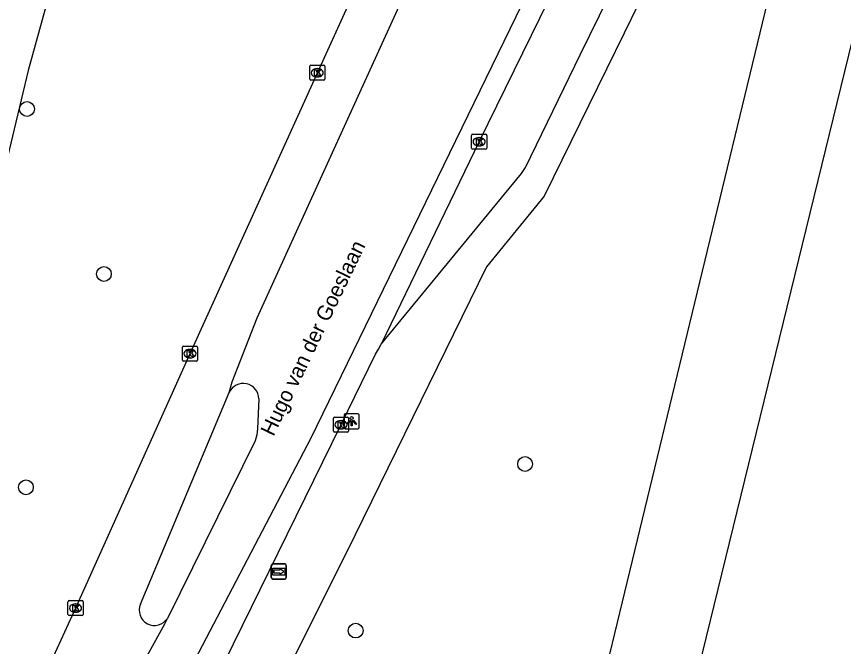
# Model space of a CAD drawing. Extents: x 163046 to 165074, y 382019 to 382874.
# Drawn here: x 163089.2 to 163144, y 382607.3 to 382649.1 of the extents above; entities that cross this region are included whole.
import ezdxf

# ---------------------------------------------------------------- set-up
doc = ezdxf.new("R2010")
doc.units = 0
for name, color, linetype in [('IMGEO_Berm_groen', 7, 'Continuous'), ('IMGEO_Boom', 7, 'Continuous'), ('IMGEO_Fietspad_open', 7, 'Continuous'), ('IMGEO_Groenvoorziening', 7, 'Continuous'), ('IMGEO_Hek', 7, 'Continuous'), ('IMGEO_Kolk', 7, 'Continuous'), ('IMGEO_Lichtpunt', 7, 'Continuous'), ('IMGEO_Openbare_ruimte_label', 7, 'Continuous'), ('IMGEO_Rijbaan_lokaal_open', 7, 'Continuous'), ('IMGEO_Voetpad_open', 7, 'Continuous'), ('IMGEO_Wegwijzer', 7, 'Continuous')]:
    doc.layers.add(name, color=color, linetype=linetype)

msp = doc.modelspace()

# ---------------------------------------------------------------- linework, layer by layer
at = {"layer": 'IMGEO_Berm_groen'}
for points in [[(163100.832, 382683.6), (163098.443, 382676.291), (163089.933, 382645.473), (163080.796, 382607.304), (163064.17, 382547.891)], [(163151.202, 382677.804), (163145.767, 382678.148), (163123.531, 382586.203), (163123.069, 382584.306), (163123.067, 382584.289), (163125.008, 382583.218)]]:
    msp.add_lwpolyline(points, dxfattribs=at)
at = {"layer": 'IMGEO_Boom'}
for centre in [(163089.857, 382642.92), (163094.96, 382631.981), (163122.898, 382619.379), (163089.782, 382617.833), (163111.661, 382608.334)]:
    msp.add_circle(centre, 0.489, dxfattribs=at)
at = {"layer": 'IMGEO_Fietspad_open'}
msp.add_lwpolyline([(163100.836, 382602.174), (163102.302, 382605.116), (163102.951, 382606.232), (163110.679, 382621.963), (163112.976, 382626.657), (163113.165, 382627.004), (163113.362, 382627.324)], dxfattribs=at)
at = {"layer": 'IMGEO_Groenvoorziening'}
msp.add_lwpolyline([(163149.986, 382672.857), (163145.369, 382650.659), (163131.6, 382594.38), (163136.619, 382593.153), (163133.378, 382579.938)], dxfattribs=at)
at = {"layer": 'IMGEO_Hek'}
msp.add_lwpolyline([(163151.202, 382677.804), (163145.767, 382678.148), (163123.531, 382586.203)], dxfattribs=at)
at = {"layer": 'IMGEO_Kolk'}
for p, q in [((163108.612, 382644.899), (163108.612, 382645.751)), ((163108.687, 382645.825), (163109.539, 382645.825)), ((163109.1, 382645.605), (163109.125, 382645.605)), ((163109.613, 382645.751), (163109.613, 382644.899)), ((163109.539, 382644.825), (163108.687, 382644.825)), ((163109.123, 382645.045), (163109.098, 382645.045)), ((163119.352, 382640.323), (163119.352, 382641.175)), ((163119.427, 382641.249), (163120.279, 382641.249)), ((163119.84, 382641.029), (163119.865, 382641.029)), ((163120.353, 382641.175), (163120.353, 382640.323)), ((163119.863, 382640.469), (163119.838, 382640.469)), ((163120.279, 382640.249), (163119.427, 382640.249)), ((163100.169, 382626.273), (163100.169, 382627.125)), ((163100.244, 382627.199), (163101.096, 382627.199)), ((163100.657, 382626.979), (163100.682, 382626.979)), ((163101.17, 382627.125), (163101.17, 382626.273)), ((163101.096, 382626.199), (163100.244, 382626.199)), ((163100.68, 382626.419), (163100.655, 382626.419)), ((163110.189, 382621.557), (163110.189, 382622.409)), ((163110.264, 382622.483), (163111.116, 382622.483)), ((163111.19, 382622.409), (163111.19, 382621.557)), ((163110.677, 382622.263), (163110.702, 382622.263)), ((163111.116, 382621.483), (163110.264, 382621.483)), ((163110.7, 382621.703), (163110.675, 382621.703)), ((163092.575, 382609.398), (163092.575, 382610.25)), ((163092.65, 382610.324), (163093.502, 382610.324)), ((163093.576, 382610.25), (163093.576, 382609.398)), ((163093.063, 382610.104), (163093.088, 382610.104)), ((163093.502, 382609.324), (163092.65, 382609.324)), ((163093.086, 382609.544), (163093.061, 382609.544))]:
    msp.add_line(p, q, dxfattribs=at)
for points in [[(163108.612, 382644.899), (163108.612, 382645.751)], [(163108.687, 382645.825), (163109.539, 382645.825)], [(163108.933, 382645.525), (163109.056, 382645.525), (163109.056, 382645.374), (163109.186, 382645.525), (163109.35, 382645.525), (163109.204, 382645.374), (163109.357, 382645.125), (163109.205, 382645.125), (163109.12, 382645.289), (163109.056, 382645.222), (163109.056, 382645.125), (163108.933, 382645.125), (163108.933, 382645.525)], [(163109.613, 382645.751), (163109.613, 382644.899)], [(163109.539, 382644.825), (163108.687, 382644.825)], [(163119.352, 382640.323), (163119.352, 382641.175)], [(163119.427, 382641.249), (163120.279, 382641.249)], [(163120.353, 382641.175), (163120.353, 382640.323)], [(163119.673, 382640.949), (163119.796, 382640.949), (163119.796, 382640.798), (163119.926, 382640.949), (163120.09, 382640.949), (163119.944, 382640.798), (163120.097, 382640.549), (163119.945, 382640.549), (163119.86, 382640.713), (163119.796, 382640.646), (163119.796, 382640.549), (163119.673, 382640.549), (163119.673, 382640.949)], [(163120.279, 382640.249), (163119.427, 382640.249)], [(163100.169, 382626.273), (163100.169, 382627.125)], [(163100.244, 382627.199), (163101.096, 382627.199)], [(163100.49, 382626.899), (163100.613, 382626.899), (163100.613, 382626.748), (163100.743, 382626.899), (163100.907, 382626.899), (163100.761, 382626.748), (163100.914, 382626.499), (163100.762, 382626.499), (163100.677, 382626.663), (163100.613, 382626.596), (163100.613, 382626.499), (163100.49, 382626.499), (163100.49, 382626.899)], [(163101.17, 382627.125), (163101.17, 382626.273)], [(163101.096, 382626.199), (163100.244, 382626.199)], [(163110.189, 382621.557), (163110.189, 382622.409)], [(163110.264, 382622.483), (163111.116, 382622.483)], [(163111.19, 382622.409), (163111.19, 382621.557)], [(163110.51, 382622.183), (163110.633, 382622.183), (163110.633, 382622.032), (163110.763, 382622.183), (163110.927, 382622.183), (163110.781, 382622.032), (163110.934, 382621.783), (163110.782, 382621.783), (163110.697, 382621.947), (163110.633, 382621.88), (163110.633, 382621.783), (163110.51, 382621.783), (163110.51, 382622.183)], [(163111.116, 382621.483), (163110.264, 382621.483)], [(163092.575, 382609.398), (163092.575, 382610.25)], [(163092.65, 382610.324), (163093.502, 382610.324)], [(163093.576, 382610.25), (163093.576, 382609.398)], [(163092.896, 382610.024), (163093.019, 382610.024), (163093.019, 382609.873), (163093.149, 382610.024), (163093.313, 382610.024), (163093.167, 382609.873), (163093.32, 382609.624), (163093.168, 382609.624), (163093.083, 382609.788), (163093.019, 382609.721), (163093.019, 382609.624), (163092.896, 382609.624), (163092.896, 382610.024)], [(163093.502, 382609.324), (163092.65, 382609.324)]]:
    msp.add_lwpolyline(points, dxfattribs=at)
for centre, start, end in [((163108.689, 382645.749), 91.552, 178.448), ((163108.689, 382645.749), 91.552, 178.448), ((163109.537, 382645.749), 1.552, 88.448), ((163109.537, 382645.749), 1.552, 88.448), ((163108.689, 382644.901), 181.552, 268.448), ((163108.689, 382644.901), 181.552, 268.448), ((163109.537, 382644.901), 271.552, 358.448), ((163109.537, 382644.901), 271.552, 358.448), ((163119.429, 382641.173), 91.552, 178.448), ((163119.429, 382641.173), 91.552, 178.448), ((163120.277, 382641.173), 1.552, 88.448), ((163120.277, 382641.173), 1.552, 88.448), ((163119.429, 382640.325), 181.552, 268.448), ((163119.429, 382640.325), 181.552, 268.448), ((163120.277, 382640.325), 271.552, 358.448), ((163120.277, 382640.325), 271.552, 358.448), ((163100.246, 382627.123), 91.552, 178.448), ((163100.246, 382627.123), 91.552, 178.448), ((163101.094, 382627.123), 1.552, 88.448), ((163101.094, 382627.123), 1.552, 88.448), ((163100.246, 382626.275), 181.552, 268.448), ((163100.246, 382626.275), 181.552, 268.448), ((163101.094, 382626.275), 271.552, 358.448), ((163101.094, 382626.275), 271.552, 358.448), ((163110.266, 382622.407), 91.552, 178.448), ((163110.266, 382622.407), 91.552, 178.448), ((163111.114, 382622.407), 1.552, 88.448), ((163111.114, 382622.407), 1.552, 88.448), ((163110.266, 382621.559), 181.552, 268.448), ((163110.266, 382621.559), 181.552, 268.448), ((163111.114, 382621.559), 271.552, 358.448), ((163111.114, 382621.559), 271.552, 358.448), ((163092.652, 382610.248), 91.552, 178.448), ((163092.652, 382610.248), 91.552, 178.448), ((163093.5, 382610.248), 1.552, 88.448), ((163093.5, 382610.248), 1.552, 88.448), ((163092.652, 382609.4), 181.552, 268.448), ((163092.652, 382609.4), 181.552, 268.448), ((163093.5, 382609.4), 271.552, 358.448), ((163093.5, 382609.4), 271.552, 358.448)]:
    msp.add_arc(centre, 0.0765, start, end, dxfattribs=at)
for centre, major_axis, ratio, start_param, end_param in [((163109.099, 382645.325), (-0.387, 0.002), 0.722429, 4.712389, 7.853982), ((163109.124, 382645.325), (-0.39, 0.002), 0.717154, 1.570796, 4.712389), ((163119.839, 382640.749), (-0.387, 0.002), 0.722429, 4.712389, 7.853982), ((163119.864, 382640.749), (-0.39, 0.002), 0.717154, 1.570796, 4.712389), ((163100.656, 382626.699), (-0.387, 0.002), 0.722429, 4.712389, 7.853982), ((163100.681, 382626.699), (-0.39, 0.002), 0.717154, 1.570796, 4.712389), ((163110.676, 382621.983), (-0.387, 0.002), 0.722429, 4.712389, 7.853982), ((163110.701, 382621.983), (-0.39, 0.002), 0.717154, 1.570796, 4.712389), ((163093.062, 382609.824), (-0.387, 0.002), 0.722429, 4.712389, 7.853982), ((163093.087, 382609.824), (-0.39, 0.002), 0.717154, 1.570796, 4.712389)]:
    msp.add_ellipse(centre, major_axis=major_axis, ratio=ratio, start_param=start_param, end_param=end_param, dxfattribs=at)
at = {"layer": 'IMGEO_Lichtpunt'}
for p, q in [((163110.896, 382622.622), (163110.896, 382621.815)), ((163110.896, 382622.622), (163110.896, 382621.815)), ((163111.798, 382622.717), (163110.99, 382622.717)), ((163111.798, 382622.717), (163110.99, 382622.717)), ((163111.892, 382621.815), (163111.892, 382622.622)), ((163111.892, 382621.815), (163111.892, 382622.622)), ((163110.99, 382621.721), (163111.798, 382621.721)), ((163110.99, 382621.721), (163111.798, 382621.721))]:
    msp.add_line(p, q, dxfattribs=at)
for points in [[(163111.27, 382622.286), (163111.309, 382622.258), (163111.121, 382621.996), (163111.083, 382622.023), (163111.27, 382622.286)], [(163111.372, 382622.238), (163111.419, 382622.238), (163111.419, 382621.916), (163111.372, 382621.916), (163111.372, 382622.238)], [(163111.482, 382622.258), (163111.52, 382622.285), (163111.707, 382622.023), (163111.668, 382621.995), (163111.482, 382622.258)]]:
    msp.add_lwpolyline(points, dxfattribs=at)
msp.add_circle((163111.395, 382622.42), 0.0994, dxfattribs=at)
for centre, start, end in [((163110.99, 382622.622), 90, 180), ((163110.99, 382622.622), 90, 180), ((163111.798, 382622.622), 0, 90), ((163111.798, 382622.622), 0, 90), ((163110.99, 382621.815), 180, 270), ((163110.99, 382621.815), 180, 270), ((163111.798, 382621.815), 270, 0), ((163111.798, 382621.815), 270, 360)]:
    msp.add_arc(centre, 0.0946, start, end, dxfattribs=at)
at = {"layer": 'IMGEO_Rijbaan_lokaal_open'}
for points in [[(163103.27, 382624.12), (163103.468, 382624.82), (163105.136, 382629.064), (163126.486, 382675.957)], [(163090.329, 382586.006), (163108.703, 382621.111), (163124.332, 382653.2), (163133.821, 382672.922)], [(163131.181, 382663.924), (163127.309, 382655.965), (163119.861, 382640.767), (163113.362, 382627.324)], [(163113.362, 382627.324), (163122.661, 382638.644), (163122.797, 382638.833), (163122.926, 382639.053), (163126.548, 382646.52), (163130.377, 382654.32), (163130.567, 382655.064), (163130.841, 382662.65)], [(163112.554, 382652.908), (163109.118, 382645.334), (163100.668, 382626.691), (163093.076, 382609.823), (163090.891, 382605.042)], [(163097.375, 382610.087), (163103.27, 382624.12)], [(163105.234, 382623.709), (163105.152, 382621.702), (163105.112, 382621.316), (163104.983, 382620.922), (163099.17, 382609.144)], [(163091.395, 382595.056), (163091.471, 382595.168), (163098.994, 382608.778), (163099.17, 382609.144)]]:
    msp.add_lwpolyline(points, dxfattribs=at)
for centre, radius, start, end in [((163104.207, 382623.698), 1.027, 0.587, 155.774), ((163098.312, 382609.691), 1.017, 157.0649, 327.5049)]:
    msp.add_arc(centre, radius, start, end, dxfattribs=at)
at = {"layer": 'IMGEO_Voetpad_open'}
msp.add_lwpolyline([(163150.799, 382678.151), (163144.015, 382679.915), (163140.434, 382677.252), (163135.61, 382663.659), (163134.269, 382660.747), (163135.515, 382660.153), (163131.747, 382652.636), (163129.465, 382647.96), (163128.293, 382645.559), (163124.156, 382637.139), (163120.335, 382632.45), (163111.066, 382613.548), (163105.142, 382601.724), (163104.494, 382600.409)], dxfattribs=at)
at = {"layer": 'IMGEO_Wegwijzer'}
for p, q in [((163106.061, 382611.851), (163106.061, 382612.651)), ((163106.061, 382612.651), (163106.061, 382611.851)), ((163106.161, 382612.751), (163106.951, 382612.751)), ((163106.951, 382612.751), (163106.161, 382612.751)), ((163107.051, 382612.651), (163107.051, 382611.851)), ((163107.051, 382611.851), (163107.051, 382612.651)), ((163106.951, 382611.751), (163106.161, 382611.751)), ((163106.161, 382611.751), (163106.951, 382611.751))]:
    msp.add_line(p, q, dxfattribs=at)
for points in [[(163106.162, 382612.483), (163106.95, 382612.483), (163106.95, 382612.019), (163106.162, 382612.019), (163106.162, 382612.483)], [(163106.227, 382612.335), (163106.227, 382612.251), (163106.227, 382612.167), (163106.638, 382612.167), (163106.638, 382612.084), (163106.885, 382612.251), (163106.638, 382612.418), (163106.638, 382612.335), (163106.227, 382612.335)]]:
    msp.add_lwpolyline(points, dxfattribs=at)
for centre, start, end in [((163106.161, 382612.651), 90, 180), ((163106.161, 382612.651), 90, 180), ((163106.951, 382612.651), 0, 90), ((163106.951, 382612.651), 360, 90), ((163106.161, 382611.851), 180, 270), ((163106.161, 382611.851), 180, 270), ((163106.951, 382611.851), 270, 0), ((163106.951, 382611.851), 270, 0)]:
    msp.add_arc(centre, 0.1, start, end, dxfattribs=at)

# ---------------------------------------------------------------- texts
at = {"layer": 'IMGEO_Openbare_ruimte_label'}
msp.add_text('Hugo van der Goeslaan', height=1, rotation=64.2805, dxfattribs=at).set_placement((163106.208, 382621.162))

doc.saveas('drawing.dxf')
